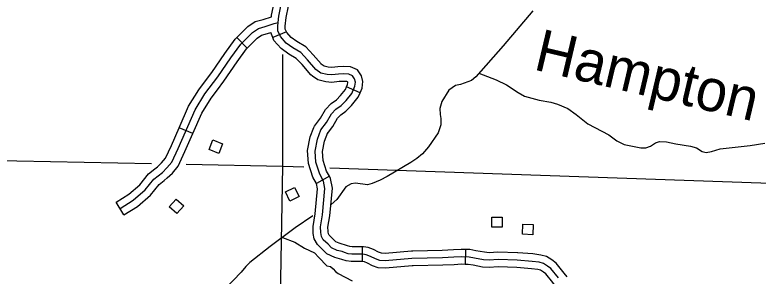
# Model space of a CAD drawing. Extents: x 1370130 to 1380143, y 377636 to 380256.
# Drawn here: x 1377176 to 1377386.4, y 379444.4 to 379518.4 of the extents above; entities that cross this region are included whole.
import ezdxf

# ---------------------------------------------------------------- set-up
doc = ezdxf.new("R2010")
doc.units = 0
for name, color, linetype in [('Level 35', 7, 'Continuous'), ('Level 45', 7, 'Continuous'), ('Level 5', 7, 'Continuous'), ('Level 56', 7, 'Continuous')]:
    doc.layers.add(name, color=color, linetype=linetype)

msp = doc.modelspace()

# ---------------------------------------------------------------- linework, layer by layer
at = {"layer": 'Level 35'}
for points in [[(1377322.62, 379519.5), (1377314.19, 379509.59), (1377306.51, 379500.85), (1377305.29, 379499.8), (1377302.2, 379498.65), (1377300.76, 379498.37), (1377298.87, 379497.1), (1377296.92, 379493.83), (1377296.29, 379491.88), (1377296.38, 379490.17), (1377296.62, 379489.06), (1377296.63, 379487.29), (1377295.79, 379484.94), (1377293.13, 379481.03), (1377291.39, 379479.03), (1377289.81, 379477.69), (1377288.09, 379476.59), (1377281.38, 379472.62), (1377279.43, 379471.62), (1377277.18, 379470.67), (1377275.88, 379470.29), (1377272.45, 379470.76), (1377271.23, 379470.52), (1377269.66, 379469.68), (1377267.19, 379466.11), (1377265.56, 379464.73)], [(1377307.37, 379501.83), (1377312.25, 379499.97), (1377315.21, 379498.59), (1377318.45, 379496.38), (1377320.27, 379495.35), (1377324.45, 379494.24), (1377327.74, 379493.71), (1377329.61, 379493.11), (1377332.5, 379491.87), (1377334.88, 379490.19), (1377338.22, 379487.53), (1377344.09, 379484.38), (1377346.38, 379482.75), (1377348.44, 379481.7), (1377353.17, 379480.75), (1377354.65, 379480.72), (1377355.92, 379481.22), (1377357.37, 379482.14), (1377358.5, 379482.54), (1377360.43, 379482.44), (1377363.05, 379481.86), (1377367.24, 379481.23), (1377368.93, 379480.7), (1377370.51, 379479.72), (1377371.69, 379479.45), (1377373.19, 379479.68), (1377375.65, 379480.47), (1377384.17, 379481.42), (1377388.31, 379482.04)], [(1377260.36, 379461.49), (1377255.4, 379458.09), (1377248.27, 379452.79), (1377242.56, 379448.24), (1377241.42, 379447.19), (1377240.06, 379445.52), (1377235.42, 379440.7)], [(1377251.75, 379455.38), (1377255.3, 379454), (1377258.01, 379452.38), (1377260.88, 379451), (1377262.05, 379449.73), (1377264.32, 379447.31), (1377265.35, 379447.15), (1377266.08, 379446.48), (1377266.78, 379445.69), (1377267.55, 379445.13), (1377271.54, 379443.09)]]:
    msp.add_lwpolyline(points, dxfattribs=at)
at = {"layer": 'Level 45'}
for p, q in [((1377252.89, 379513.61), (1377249.01, 379511.99)), ((1377241.76, 379508.94), (1377238.82, 379511.94)), ((1377273.75, 379496.31), (1377269.9, 379497.98)), ((1377226.4, 379484.75), (1377222.55, 379486.44)), ((1377265.05, 379472.69), (1377261.37, 379470.66)), ((1377206.9, 379461.81), (1377204.71, 379465.4)), ((1377274.34, 379452.73), (1377274.34, 379448.53)), ((1377303.56, 379451.95), (1377303.43, 379447.76))]:
    msp.add_line(p, q, dxfattribs=at)
for points in [[(1377248.63, 379517.84), (1377248.69, 379518.32), (1377249.39, 379521.75), (1377250.01, 379524.17), (1377250.99, 379527.75)], [(1377252.89, 379513.61), (1377252.58, 379514.35), (1377252.54, 379515.21), (1377252.84, 379517.64), (1377253.48, 379520.81), (1377254.07, 379523.09), (1377255.04, 379526.65)], [(1377329.91, 379443.91), (1377327.76, 379446.6), (1377326.82, 379447.27), (1377325.61, 379448.01), (1377324.46, 379448.34), (1377322.45, 379448.61), (1377318.22, 379448.95), (1377312.77, 379449.15), (1377310.29, 379448.95), (1377308.68, 379449.08), (1377306.12, 379449.55), (1377304.58, 379449.82), (1377302.36, 379449.89), (1377300.28, 379449.76), (1377297.05, 379449.62), (1377288.39, 379449.42), (1377280.86, 379448.75), (1377279.32, 379448.81), (1377278.11, 379449.29), (1377276.7, 379450.02), (1377275.49, 379450.5), (1377274.55, 379450.63), (1377272.94, 379450.63), (1377271.39, 379450.63), (1377270.32, 379450.76), (1377269.37, 379451.1), (1377268.7, 379451.44), (1377267.22, 379451.7), (1377265.61, 379452.44), (1377264.67, 379453.52), (1377263.33, 379454.73), (1377262.79, 379455.67), (1377262.59, 379456.75), (1377262.52, 379458.36), (1377263.06, 379461.79), (1377263.8, 379469.25), (1377263.4, 379471.33), (1377262.32, 379473.28), (1377261.18, 379476.71), (1377260.98, 379479.8), (1377261.65, 379483.23), (1377262.66, 379485.85), (1377264.27, 379487.94), (1377265.61, 379490.36), (1377266.89, 379491.7), (1377268.37, 379492.71), (1377269.78, 379494.12), (1377271.39, 379496.14), (1377272.26, 379498.15), (1377272.4, 379499.36), (1377272.2, 379500.24), (1377271.59, 379501.11), (1377270.52, 379501.58), (1377269.04, 379501.65), (1377267.63, 379501.58), (1377265.75, 379501.38), (1377264.4, 379501.52), (1377262.66, 379501.92), (1377261.25, 379502.93), (1377258.89, 379505.68), (1377257.01, 379507.7), (1377254.73, 379509.04), (1377252.78, 379510.39), (1377251.17, 379512.27), (1377250.5, 379513.88), (1377250.43, 379515.3), (1377250.77, 379517.98), (1377251.44, 379521.28)], [(1377238.82, 379511.94), (1377242, 379515.05), (1377244.09, 379516.45), (1377246.29, 379517.08), (1377248.63, 379517.84)], [(1377205.8, 379463.61), (1377209.52, 379465.88), (1377212.89, 379468.84), (1377215.37, 379471.87), (1377217.78, 379473.8), (1377219.09, 379475.04), (1377220.47, 379476.7), (1377222.26, 379480.55), (1377227.08, 379491.51), (1377229.83, 379495.99), (1377233.48, 379500.88), (1377237.2, 379506.25), (1377239.95, 379510.11), (1377243.33, 379513.42), (1377244.98, 379514.52), (1377246.91, 379515.07), (1377249.45, 379515.9), (1377250.54, 379516.22)], [(1377241.76, 379508.94), (1377244.66, 379511.78), (1377245.87, 379512.59), (1377247.52, 379513.06), (1377248.44, 379513.36)], [(1377249.01, 379511.99), (1377248.44, 379513.36)], [(1377262.74, 379504.44), (1377262.68, 379504.49), (1377260.46, 379507.08), (1377258.34, 379509.35), (1377255.86, 379510.82), (1377254.2, 379511.96), (1377252.98, 379513.38), (1377252.89, 379513.61)], [(1377229.98, 379499.7), (1377231.77, 379502.1), (1377235.48, 379507.46), (1377238.35, 379511.48), (1377238.82, 379511.94)], [(1377260.29, 379501.03), (1377259.82, 379501.37), (1377257.33, 379504.28), (1377255.69, 379506.04), (1377253.6, 379507.27), (1377251.36, 379508.81), (1377249.36, 379511.16), (1377249.01, 379511.99)], [(1377233.35, 379497.19), (1377235.19, 379499.65), (1377238.92, 379505.04), (1377241.55, 379508.74), (1377241.76, 379508.94)], [(1377273.75, 379496.31), (1377274.32, 379497.61), (1377274.52, 379499.49), (1377274.15, 379501.1), (1377272.98, 379502.8), (1377271, 379503.66), (1377269.04, 379503.75), (1377267.47, 379503.68), (1377265.74, 379503.49), (1377264.75, 379503.59), (1377263.54, 379503.87), (1377262.74, 379504.44)], [(1377269.9, 379497.98), (1377270.21, 379498.7), (1377270.27, 379499.24), (1377270.24, 379499.37), (1377270.2, 379499.43), (1377270.03, 379499.5), (1377269.04, 379499.55), (1377267.79, 379499.49), (1377265.75, 379499.27), (1377264.06, 379499.44), (1377261.78, 379499.97), (1377260.29, 379501.03)], [(1377222.55, 379486.44), (1377225.21, 379492.49), (1377228.09, 379497.17), (1377229.98, 379499.7)], [(1377226.4, 379484.75), (1377228.94, 379490.53), (1377231.57, 379494.81), (1377233.35, 379497.19)], [(1377260.67, 379486.54), (1377260.81, 379486.89), (1377262.51, 379489.1), (1377263.91, 379491.61), (1377265.52, 379493.31), (1377267.02, 379494.33), (1377268.21, 379495.52), (1377269.57, 379497.23), (1377269.9, 379497.98)], [(1377264.51, 379484.81), (1377266.03, 379486.78), (1377267.32, 379489.1), (1377268.26, 379490.09), (1377269.71, 379491.09), (1377271.35, 379492.72), (1377273.21, 379495.05), (1377273.75, 379496.31)], [(1377215.64, 379474.78), (1377216.4, 379475.39), (1377217.56, 379476.48), (1377218.68, 379477.83), (1377220.34, 379481.42), (1377222.55, 379486.44)], [(1377261.37, 379470.66), (1377260.39, 379472.44), (1377259.1, 379476.3), (1377258.86, 379479.94), (1377259.62, 379483.81), (1377260.67, 379486.54)], [(1377218.26, 379471.5), (1377219.16, 379472.22), (1377220.62, 379473.6), (1377222.26, 379475.56), (1377224.17, 379479.69), (1377226.4, 379484.75)], [(1377265.05, 379472.69), (1377264.25, 379474.13), (1377263.26, 379477.12), (1377263.09, 379479.67), (1377263.67, 379482.65), (1377264.59, 379485.04)], [(1377204.71, 379465.4), (1377208.27, 379467.58), (1377211.38, 379470.31), (1377213.89, 379473.37), (1377215.64, 379474.78)], [(1377206.9, 379461.81), (1377210.77, 379464.18), (1377214.41, 379467.38), (1377216.86, 379470.37), (1377218.26, 379471.5)], [(1377264.67, 379457.14), (1377264.63, 379458.24), (1377265.14, 379461.52), (1377265.92, 379469.35), (1377265.39, 379472.06), (1377265.05, 379472.69)], [(1377260.48, 379456.97), (1377260.42, 379458.48), (1377260.98, 379462.05), (1377261.68, 379469.15), (1377261.4, 379470.61), (1377261.37, 379470.66)], [(1377274.34, 379448.53), (1377272.94, 379448.53), (1377271.26, 379448.53), (1377269.83, 379448.71), (1377268.55, 379449.17), (1377266.59, 379449.69), (1377264.33, 379450.72), (1377261.67, 379453.4), (1377260.79, 379454.94), (1377260.5, 379456.51), (1377260.48, 379456.97)], [(1377274.34, 379452.73), (1377272.94, 379452.73), (1377271.52, 379452.73), (1377270.8, 379452.82), (1377270.2, 379453.03), (1377267.86, 379453.72), (1377266.9, 379454.17), (1377264.98, 379456.06), (1377264.79, 379456.41), (1377264.68, 379456.98), (1377264.67, 379457.14)], [(1377288.68, 379451.53), (1377288.27, 379451.52), (1377280.82, 379450.85), (1377279.76, 379450.9), (1377278.98, 379451.2), (1377277.57, 379451.94), (1377276.02, 379452.54), (1377274.7, 379452.73), (1377274.34, 379452.73)], [(1377303.56, 379451.95), (1377302.33, 379451.99), (1377300.17, 379451.85), (1377296.99, 379451.72), (1377288.68, 379451.53)], [(1377318.28, 379451.05), (1377312.73, 379451.25), (1377310.29, 379451.06), (1377308.95, 379451.17), (1377306.49, 379451.62), (1377304.79, 379451.92), (1377303.56, 379451.95)], [(1377332.34, 379444.23), (1377331.54, 379445.22), (1377329.21, 379448.14), (1377327.98, 379449.02), (1377326.47, 379449.94), (1377324.9, 379450.4), (1377322.67, 379450.7), (1377318.34, 379451.05), (1377318.27, 379451.05)], [(1377288.77, 379447.33), (1377288.51, 379447.32), (1377280.91, 379446.64), (1377278.88, 379446.73), (1377277.24, 379447.37), (1377275.83, 379448.11), (1377274.95, 379448.45), (1377274.4, 379448.53), (1377274.34, 379448.53)], [(1377303.43, 379447.76), (1377302.4, 379447.79), (1377300.39, 379447.66), (1377297.12, 379447.52), (1377288.77, 379447.33)], [(1377318.12, 379446.85), (1377312.82, 379447.05), (1377310.29, 379446.84), (1377308.4, 379447), (1377305.75, 379447.49), (1377304.37, 379447.73), (1377303.43, 379447.76)], [(1377329.08, 379441.59), (1377328.27, 379442.59), (1377326.3, 379445.06), (1377325.66, 379445.52), (1377324.75, 379446.07), (1377324.03, 379446.28), (1377322.23, 379446.52), (1377318.1, 379446.85), (1377318.12, 379446.85)]]:
    msp.add_lwpolyline(points, dxfattribs=at)
at = {"layer": 'Level 5'}
for points in [[(1377251.76, 379507.2), (1377251.74, 379475.59)], [(1377119.37, 379478.16), (1377214.75, 379476.3)], [(1377224.5, 379476.12), (1377251.74, 379475.59)], [(1377251.74, 379475.59), (1377249.98, 379374.42)], [(1377251.74, 379475.59), (1377257.81, 379475.37)], [(1377265.16, 379475.11), (1377397.99, 379470.43)]]:
    msp.add_lwpolyline(points, dxfattribs=at)
at = {"layer": 'Level 56'}
for points in [[(1377234.77, 379481.9), (1377233.72, 379479.18), (1377230.99, 379480.24), (1377232.05, 379482.96)], [(1377255.21, 379469.55), (1377256.51, 379466.95), (1377253.9, 379465.64), (1377252.59, 379468.25)], [(1377219.74, 379464.07), (1377221.68, 379466.24), (1377223.86, 379464.3), (1377221.92, 379462.12)], [(1377313.94, 379461.15), (1377313.94, 379458.24), (1377311.02, 379458.24), (1377311.02, 379461.15)], [(1377322.72, 379459.06), (1377322.59, 379456.14), (1377319.67, 379456.27), (1377319.8, 379459.18)]]:
    msp.add_lwpolyline(points, close=True, dxfattribs=at)

# ---------------------------------------------------------------- texts
at = {"layer": 'Level 35'}
for s, rotation, p in [('Hampton', 346.7087, (1377322.5, 379502.98)), ('Georges', 344.6424, (1377126.8, 379437.15))]:
    msp.add_text(s, height=11.827, rotation=rotation, dxfattribs=at).set_placement(p)

doc.saveas('drawing.dxf')
